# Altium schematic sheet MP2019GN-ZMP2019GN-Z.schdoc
size 127 x 101 mm
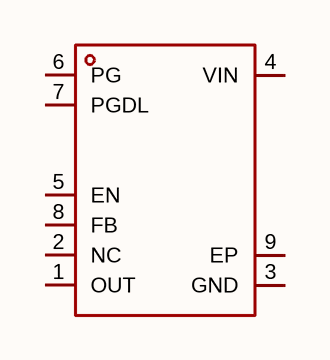
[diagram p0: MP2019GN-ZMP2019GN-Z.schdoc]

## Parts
U?  mp2019gn-z  [SOIC-8_L4.9-W3.9-P1.27-LS6.0-BL-EP3.4]  (value not drawn)

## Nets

Not connected (* = marked no-connect by the designer): U? 1(OUT) 2(NC) 3(GND) 4(VIN) 5(EN) 6(PG) 7(PGDL) 8(FB) 9(EP)

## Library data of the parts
U? = mp2019gn-z: 输出极性:正极;工作电压:40V;输出电压:1.25V~15V;输出电流:300mA;电源纹波抑制比(PSRR):51dB@(1kHz);输出类型:可调;; Manufacturer: MPS(芯源); AddInBom: yes; ModelId: d197e284ea6e430f9c732504127547ac; ModelTransform: 192.913,236.22,0,0,0,0,0,0,0; Output Configuration: 正极; Voltage - Supply: 40V; Output Current: 300mA; Voltage Dropout: 550mV@(300mA); standby current: 10uA; Output Type: 可调; Number of Outputs: 1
